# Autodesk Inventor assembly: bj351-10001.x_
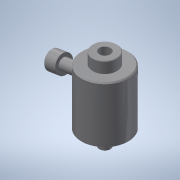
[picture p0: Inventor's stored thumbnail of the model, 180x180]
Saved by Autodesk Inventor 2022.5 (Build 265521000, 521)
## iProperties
Part Number: bj351-10001.x_
Material: 一般
Document SubType Name: Assembly
Designer: ImaoCorp
Sending System: SOLIDWORKS 2017-2017317
MC: AMD64
MC_MODEL: Intel64 Family 6 Model 60 Stepping 3, GenuineIntel
OS: Windows_NT
FRU: Parasolid Version 29.0, build 201,  4-17-2017
FORMAT: text
GUISE: transmit
KEY: bj351-10001
FILE: bj351-10001.x_t
DATE: Fri Mar 15 10:12:36 2019
Author: ImaoCorp
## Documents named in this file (4)
- X:\14_SW2022-Inv2022\00_全2023-1023新製品(TCC)まで\b\bj351-10001\BJ351-10001.iam
- X:\14_SW2022-Inv2022\00_全2023-1023新製品(TCC)まで\b\bj351-10001\bj351-10001_01.ipt
- X:\14_SW2022-Inv2022\00_全2023-1023新製品(TCC)まで\b\bj351-10001\bj351-10001_02.ipt
- X:\14_SW2022-Inv2022\00_全2023-1023新製品(TCC)まで\b\bj351-10001\bj351-10001_03.ipt
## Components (3 placed, 3 different names)
1. bj351-10001_01
2. bj351-10001_02
3. bj351-10001_03
